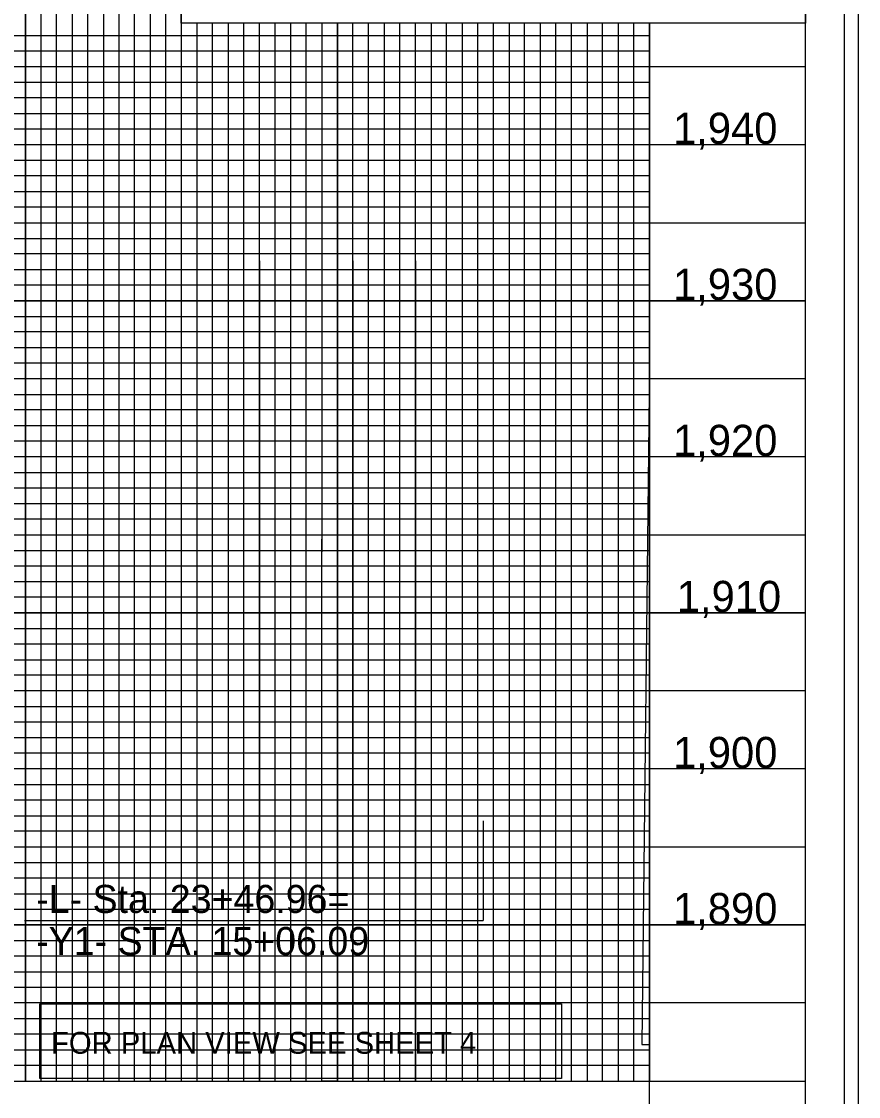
# Model space of a CAD drawing. Extents: x 557032 to 558716, y 513430 to 514605.
# Drawn here: x 558448.2 to 558716.5, y 514000.4 to 514344.9 of the extents above; entities that cross this region are included whole.
import ezdxf

# ---------------------------------------------------------------- set-up
doc = ezdxf.new("R2010")
doc.units = 0
for name, color, linetype in [('Exist Vertical Profile Vertical Axis Label', 7, 'Continuous'), ('Prop VPI Label', 7, 'Continuous'), ('Scratch_Level_5', 7, 'Continuous'), ('Sheet DOT Grid CELL', 7, 'Continuous'), ('Sheet Layout Profile Border Port 1', 7, 'Continuous'), ('Sheet Plot Border Inside CELL', 7, 'Continuous'), ('Sheet Plot Border Outside CELL', 7, 'Continuous'), ('Sheet Profile CELL', 7, 'Continuous'), ('Sheet Profile Grid Major CELL', 7, 'Continuous'), ('Sheet Profile Grid Middle CELL', 7, 'Continuous'), ('Sheet Profile Grid Minor CELL', 7, 'Continuous'), ('Sheet Sticker Exception Certification CELL', 7, 'Continuous')]:
    doc.layers.add(name, color=color, linetype=linetype)

msp = doc.modelspace()

# ---------------------------------------------------------------- linework, layer by layer
at = {"layer": 'Prop VPI Label'}
for p in [(558596.13, 514088.8), (558449.21, 514056.88)]:
    msp.add_line(p, (558596.2, 514056.88), dxfattribs=at)
msp.add_lwpolyline([(558454.04, 514030.1), (558621.32, 514030.1), (558621.32, 514006.16), (558454.04, 514006.16)], close=True, dxfattribs=at)
msp.add_lwpolyline([(558454.04, 514030.1), (558621.32, 514030.1), (558621.32, 514006.16), (558454.04, 514006.16)], close=True, dxfattribs=at)
at = {"layer": 'Scratch_Level_5'}
for p, q in [((558649.45, 514235.4), (558646.99, 514017.12)), ((558649.45, 514017.12), (558649.45, 514235.4)), ((558646.99, 514017.12), (558649.45, 514017.12))]:
    msp.add_line(p, q, dxfattribs=at)
msp.add_lwpolyline([(557207.08, 514505.4), (557207.08, 513980.4), (558649.45, 513980.4), (558649.45, 514344.35), (558499.4, 514344.35), (558499.4, 514505.4)], close=True, dxfattribs=at)
at = {"layer": 'Sheet DOT Grid CELL'}
for p, q in [((558449.45, 514005.4), (558449.45, 514505.4)), ((558449.45, 514036.11), (558449.45, 514488.82)), ((558499.45, 514005.4), (558499.45, 514367.85)), ((558549.45, 514005.4), (558549.45, 514344.35)), ((558599.45, 514005.4), (558599.45, 514344.35)), ((558649.45, 514005.4), (558649.45, 514344.35)), ((558649.45, 514017.12), (558649.45, 514325.22)), ((558599.45, 514039.15), (558599.45, 514322.81)), ((558499.45, 514037.12), (558499.45, 514318.01)), ((558549.45, 514038.14), (558549.45, 514320.41)), ((558699.45, 514305.4), (557199.45, 514305.4)), ((558693.5, 514305.4), (557204.01, 514305.4)), ((558699.45, 514255.4), (557199.45, 514255.4)), ((558693.5, 514255.4), (557204.1, 514255.4)), ((558699.45, 514205.4), (557199.45, 514205.4)), ((558693.5, 514205.4), (557204.18, 514205.4)), ((558699.45, 514155.4), (557199.45, 514155.4)), ((558693.5, 514155.4), (557204.27, 514155.4)), ((558699.45, 514105.4), (557199.45, 514105.4)), ((558693.5, 514105.4), (557204.36, 514105.4)), ((558699.45, 514055.4), (557199.45, 514055.4)), ((558693.5, 514055.4), (557204.45, 514055.4))]:
    msp.add_line(p, q, dxfattribs=at)
at = {"layer": 'Sheet Layout Profile Border Port 1'}
for points in [[(557249.45, 514344.35), (557249.45, 514005.4), (558649.45, 514005.4), (558649.45, 514344.35)], [(558649.45, 514017.12), (558649.45, 514325.22)]]:
    msp.add_lwpolyline(points, dxfattribs=at)
at = {"layer": 'Sheet Plot Border Inside CELL'}
msp.add_lwpolyline([(557045.45, 513452.85), (558711.95, 513452.85), (558711.95, 514507.95), (557045.45, 514507.95)], close=True, dxfattribs=at)
at = {"layer": 'Sheet Plot Border Outside CELL'}
msp.add_lwpolyline([(557032.45, 513430.4), (558716.45, 513430.4), (558716.45, 514530.4), (557032.45, 514530.4)], close=True, dxfattribs=at)
at = {"layer": 'Sheet Profile CELL'}
msp.add_line((557199.45, 514005.4), (558699.45, 514005.4), dxfattribs=at)
msp.add_lwpolyline([(558699.45, 514505.4), (557199.45, 514505.4), (557199.45, 513455.4), (558699.45, 513455.4)], close=True, dxfattribs=at)
at = {"layer": 'Sheet Profile Grid Major CELL'}
for points in [[(557949.45, 514005.4), (557999.45, 514005.4), (557999.45, 514505.4), (558049.45, 514505.4), (558049.45, 514005.4), (558099.45, 514005.4), (558099.45, 514505.4), (558149.45, 514505.4), (558149.45, 514005.4), (558199.45, 514005.4), (558199.45, 514505.4), (558249.45, 514505.4), (558249.45, 514005.4), (558299.45, 514005.4), (558299.45, 514505.4), (558349.45, 514505.4), (558349.45, 514005.4), (558399.45, 514005.4), (558399.45, 514505.4), (558449.45, 514505.4), (558449.45, 514005.4), (558499.45, 514005.4), (558499.45, 514505.4), (558525.75, 514505.4)], [(558449.45, 514488.82), (558449.45, 514036.11)], [(558649.45, 514344.35), (558649.45, 514005.4), (558699.45, 514005.4), (558699.45, 514355.4)], [(558549.45, 514344.35), (558549.45, 514005.4), (558599.45, 514005.4), (558599.45, 514005.4), (558599.45, 514344.35)], [(558649.45, 514325.22), (558649.45, 514017.12)], [(558599.45, 514039.15), (558599.45, 514322.81)], [(558499.45, 514037.12), (558499.45, 514318.01)], [(558549.45, 514320.41), (558549.45, 514038.14)], [(558699.45, 514305.4), (557199.45, 514305.4), (557199.45, 514255.4), (558699.45, 514255.4)], [(558693.5, 514305.4), (557204.01, 514305.4)], [(557204.1, 514255.4), (558693.5, 514255.4)], [(558699.45, 514205.4), (557199.45, 514205.4), (557199.45, 514155.4), (558699.45, 514155.4)], [(558693.5, 514205.4), (557204.18, 514205.4)], [(557204.27, 514155.4), (558693.5, 514155.4)], [(558699.45, 514105.4), (557199.45, 514105.4), (557199.45, 514105.4), (557199.45, 514055.4), (558699.45, 514055.4)], [(558693.5, 514105.4), (557204.36, 514105.4)], [(557204.45, 514055.4), (558693.5, 514055.4)]]:
    msp.add_lwpolyline(points, dxfattribs=at)
at = {"layer": 'Sheet Profile Grid Middle CELL'}
for points in [[(558424.45, 514505.4), (558474.45, 514505.4), (558474.45, 514005.4), (558524.45, 514005.4), (558524.45, 514344.35)], [(558474.45, 514488.82), (558474.45, 514036.62)], [(558524.45, 514268.2), (558524.45, 514005.4), (558574.45, 514005.4), (558574.45, 514344.35)], [(558574.45, 514268.2), (558574.45, 514005.4), (558624.45, 514005.4), (558624.45, 514344.35)], [(558699.45, 514330.4), (557199.45, 514330.4), (557199.45, 514280.4), (558524.45, 514280.4)], [(558484.51, 514330.4), (557203.96, 514330.4)], [(558574.45, 514038.64), (558574.45, 514321.61)], [(558624.45, 514031.91), (558624.45, 514324.01)], [(558524.45, 514037.63), (558524.45, 514319.21)], [(557204.05, 514280.4), (558524.45, 514280.4)], [(558524.45, 514280.4), (558699.45, 514280.4)], [(558524.45, 514280.4), (558693.5, 514280.4)], [(558524.45, 514268.2), (558524.45, 514037.63)], [(558574.45, 514268.2), (558574.45, 514038.64)], [(558699.45, 514230.4), (557199.45, 514230.4), (557199.45, 514180.4), (558699.45, 514180.4)], [(558693.5, 514230.4), (557204.14, 514230.4)], [(557204.23, 514180.4), (558693.5, 514180.4)], [(558699.45, 514130.4), (557199.45, 514130.4), (557199.45, 514080.4), (558699.45, 514080.4)], [(558693.5, 514130.4), (557204.32, 514130.4)], [(557204.4, 514080.4), (558693.5, 514080.4)], [(558699.45, 514030.4), (557199.45, 514030.4)], [(558693.5, 514030.4), (558625.78, 514030.4)]]:
    msp.add_lwpolyline(points, dxfattribs=at)
at = {"layer": 'Sheet Profile Grid Minor CELL'}
for p, q in [((557249.45, 514340.4), (558649.45, 514340.4)), ((557249.45, 514340.4), (558484.51, 514340.4)), ((558649.45, 514320.4), (557249.45, 514320.4)), ((558484.51, 514320.4), (557249.45, 514320.4)), ((558649.45, 514320.4), (558549.26, 514320.4)), ((557249.45, 514315.4), (558649.45, 514315.4)), ((557249.45, 514315.4), (558649.45, 514315.4)), ((558649.45, 514295.4), (557249.45, 514295.4)), ((558649.45, 514295.4), (557249.45, 514295.4)), ((557249.45, 514290.4), (558649.45, 514290.4)), ((557249.45, 514290.4), (558649.45, 514290.4)), ((558649.45, 514270.4), (557249.45, 514270.4)), ((558649.45, 514270.4), (557249.45, 514270.4)), ((557249.45, 514265.4), (558649.45, 514265.4)), ((557249.45, 514265.4), (558649.45, 514265.4)), ((558649.45, 514260.4), (557249.45, 514260.4)), ((558649.45, 514260.4), (557249.45, 514260.4)), ((557249.45, 514250.4), (558649.45, 514250.4)), ((557249.45, 514250.4), (558649.45, 514250.4)), ((558649.45, 514245.4), (557249.45, 514245.4)), ((558649.45, 514245.4), (557249.45, 514245.4)), ((557249.45, 514240.4), (558649.45, 514240.4)), ((557249.45, 514240.4), (558649.45, 514240.4)), ((558649.45, 514235.4), (557249.45, 514235.4)), ((558649.45, 514235.4), (557249.45, 514235.4)), ((557249.45, 514225.4), (558649.45, 514225.4)), ((557249.45, 514225.4), (558649.45, 514225.4)), ((558649.45, 514220.4), (557249.45, 514220.4)), ((558649.45, 514220.4), (557249.45, 514220.4)), ((557249.45, 514215.4), (558649.45, 514215.4)), ((557249.45, 514215.4), (558649.45, 514215.4)), ((558649.45, 514210.4), (557249.45, 514210.4)), ((558649.45, 514210.4), (557249.45, 514210.4)), ((557249.45, 514200.4), (558649.45, 514200.4)), ((557249.45, 514200.4), (558649.45, 514200.4)), ((558649.45, 514195.4), (557249.45, 514195.4)), ((558649.45, 514195.4), (557249.45, 514195.4)), ((557249.45, 514190.4), (558649.45, 514190.4)), ((557249.45, 514190.4), (558649.45, 514190.4)), ((558649.45, 514185.4), (557249.45, 514185.4)), ((558649.45, 514185.4), (557249.45, 514185.4)), ((557249.45, 514175.4), (558649.45, 514175.4)), ((557249.45, 514175.4), (558649.45, 514175.4)), ((558649.45, 514170.4), (557249.45, 514170.4)), ((558649.45, 514170.4), (557249.45, 514170.4)), ((557249.45, 514165.4), (558649.45, 514165.4)), ((557249.45, 514165.4), (558649.45, 514165.4)), ((558649.45, 514160.4), (557249.45, 514160.4)), ((558649.45, 514160.4), (557249.45, 514160.4)), ((557249.45, 514150.4), (558649.45, 514150.4)), ((557249.45, 514150.4), (558649.45, 514150.4)), ((558649.45, 514145.4), (557249.45, 514145.4)), ((558649.45, 514145.4), (557249.45, 514145.4)), ((557249.45, 514140.4), (558649.45, 514140.4)), ((557249.45, 514140.4), (558649.45, 514140.4)), ((558649.45, 514135.4), (557249.45, 514135.4)), ((558649.45, 514135.4), (557249.45, 514135.4)), ((557249.45, 514125.4), (558649.45, 514125.4)), ((557249.45, 514125.4), (558649.45, 514125.4)), ((558649.45, 514120.4), (557249.45, 514120.4)), ((558649.45, 514120.4), (557249.45, 514120.4)), ((558649.45, 514115.4), (557249.45, 514115.4)), ((558649.45, 514115.4), (557249.45, 514115.4)), ((558649.45, 514110.4), (557249.45, 514110.4)), ((558649.45, 514110.4), (557249.45, 514110.4)), ((557249.45, 514100.4), (558649.45, 514100.4)), ((557249.45, 514100.4), (558649.45, 514100.4)), ((558649.45, 514095.4), (557249.45, 514095.4)), ((558649.45, 514095.4), (557249.45, 514095.4)), ((557249.45, 514090.4), (558649.45, 514090.4)), ((557249.45, 514090.4), (558649.45, 514090.4)), ((558649.45, 514085.4), (557249.45, 514085.4)), ((558649.45, 514085.4), (557249.45, 514085.4)), ((557249.45, 514075.4), (558649.45, 514075.4)), ((557249.45, 514075.4), (558649.45, 514075.4)), ((558649.45, 514070.4), (557249.45, 514070.4)), ((558649.45, 514070.4), (557249.45, 514070.4)), ((557249.45, 514065.4), (558649.45, 514065.4)), ((557249.45, 514065.4), (558649.45, 514065.4)), ((558649.45, 514060.4), (557249.45, 514060.4)), ((558649.45, 514060.4), (557249.45, 514060.4)), ((557249.45, 514050.4), (558649.45, 514050.4)), ((557249.45, 514050.4), (558649.45, 514050.4)), ((558649.45, 514045.4), (557249.45, 514045.4)), ((558649.45, 514045.4), (557249.45, 514045.4)), ((557249.45, 514040.4), (558649.45, 514040.4)), ((557249.45, 514040.4), (558649.45, 514040.4)), ((558649.45, 514035.4), (557249.45, 514035.4)), ((558649.45, 514035.4), (558621.36, 514035.4)), ((557249.45, 514025.4), (558649.45, 514025.4)), ((558630.2, 514025.4), (558649.45, 514025.4)), ((558649.45, 514020.4), (557249.45, 514020.4)), ((558649.45, 514020.4), (558634.63, 514020.4)), ((557249.45, 514015.4), (558649.45, 514015.4))]:
    msp.add_line(p, q, dxfattribs=at)
for points in [[(558444.45, 514505.4), (558454.45, 514505.4), (558454.45, 514005.4), (558459.45, 514005.4), (558459.45, 514505.4), (558464.45, 514505.4), (558464.45, 514005.4), (558469.45, 514005.4), (558469.45, 514505.4), (558479.45, 514505.4), (558479.45, 514005.4), (558484.45, 514005.4), (558484.45, 514505.4), (558489.45, 514505.4), (558489.45, 514005.4), (558494.45, 514005.4), (558494.45, 514505.4), (558504.45, 514505.4)], [(558454.45, 514488.82), (558454.45, 514036.21)], [(558459.45, 514036.31), (558459.45, 514488.82)], [(558464.45, 514488.82), (558464.45, 514036.42)], [(558469.45, 514036.52), (558469.45, 514488.82)], [(558479.45, 514488.82), (558479.45, 514036.72)], [(558484.45, 514036.82), (558484.45, 514488.82)], [(558504.45, 514344.35), (558504.45, 514005.4), (558509.45, 514005.4), (558509.45, 514344.35)], [(558514.45, 514344.35), (558514.45, 514005.4), (558519.45, 514005.4), (558519.45, 514344.35)], [(558529.45, 514344.35), (558529.45, 514005.4), (558529.45, 514005.4), (558534.45, 514005.4), (558539.45, 514005.4), (558539.45, 514344.35)], [(558534.45, 514344.35), (558534.45, 514005.4)], [(558544.45, 514344.35), (558544.35, 514005.45), (558549.35, 514005.45), (558554.45, 514005.4), (558554.45, 514344.35)], [(558554.45, 514268.2), (558554.45, 514005.4), (558559.45, 514005.4), (558559.45, 514344.35)], [(558564.45, 514344.35), (558564.45, 514005.4), (558569.45, 514005.4), (558569.45, 514344.35)], [(558579.45, 514344.35), (558579.45, 514005.4), (558584.45, 514005.4), (558584.45, 514344.35)], [(558589.45, 514344.35), (558589.45, 514005.4), (558594.45, 514005.4), (558594.45, 514344.35)], [(558604.45, 514344.35), (558604.45, 514005.4), (558609.45, 514005.4), (558609.45, 514344.35)], [(558614.45, 514344.35), (558614.45, 514005.4), (558619.45, 514005.4), (558619.45, 514344.35)], [(558629.45, 514344.35), (558629.45, 514005.4), (558634.45, 514005.4), (558634.45, 514344.35)], [(558639.45, 514344.35), (558639.45, 514005.4), (558644.45, 514005.4), (558644.45, 514344.35)], [(558649.45, 514335.4), (557249.45, 514335.4), (557249.45, 514325.4), (558649.45, 514325.4)], [(558484.51, 514335.4), (557249.45, 514335.4), (557249.45, 514325.4), (558484.51, 514325.4)], [(558629.45, 514324.25), (558629.45, 514026.25)], [(558634.45, 514020.59), (558634.45, 514324.49)], [(558639.45, 514324.74), (558639.45, 514017.12)], [(558644.45, 514017.12), (558644.45, 514324.98)], [(558559.45, 514038.34), (558559.45, 514320.89)], [(558564.45, 514321.13), (558564.45, 514038.44)], [(558569.45, 514038.54), (558569.45, 514321.37)], [(558579.45, 514321.85), (558579.45, 514038.75)], [(558584.45, 514038.85), (558584.45, 514322.09)], [(558589.45, 514322.33), (558589.45, 514038.95)], [(558594.45, 514039.05), (558594.45, 514322.57)], [(558604.45, 514323.05), (558604.45, 514039.25)], [(558609.45, 514039.35), (558609.45, 514323.29)], [(558614.45, 514323.53), (558614.45, 514039.46)], [(558619.45, 514037.56), (558619.45, 514323.77)], [(558489.45, 514317.53), (558489.45, 514036.92)], [(558494.45, 514037.02), (558494.45, 514317.77)], [(558504.45, 514318.25), (558504.45, 514037.23)], [(558509.45, 514037.33), (558509.45, 514318.49)], [(558514.45, 514318.73), (558514.45, 514037.43)], [(558519.45, 514037.53), (558519.45, 514318.97)], [(558529.45, 514319.45), (558529.45, 514037.73)], [(558534.45, 514319.69), (558534.45, 514037.83)], [(558539.45, 514037.94), (558539.45, 514319.93)], [(558544.44, 514320.17), (558544.36, 514038.04)], [(558554.45, 514038.24), (558554.45, 514320.65)], [(558649.45, 514310.4), (557249.45, 514310.4), (557249.45, 514300.4), (558649.45, 514300.4)], [(558649.45, 514310.4), (557249.45, 514310.4), (557249.45, 514300.4), (558649.45, 514300.4)], [(558649.45, 514285.4), (557249.45, 514285.4), (557249.45, 514275.4), (558649.45, 514275.4)], [(558649.45, 514285.4), (557249.45, 514285.4), (557249.45, 514275.4), (558649.45, 514275.4)], [(558554.45, 514268.2), (558554.45, 514038.24)], [(558649.45, 514010.4), (557249.45, 514010.4)]]:
    msp.add_lwpolyline(points, dxfattribs=at)
at = {"layer": 'Sheet Sticker Exception Certification CELL'}
for p, q in [((558499.4, 514344.35), (558499.4, 514367.85)), ((558499.4, 514344.35), (558499.4, 514367.85)), ((558699.44, 514367.84), (558699.44, 514344.34)), ((558699.44, 514367.84), (558699.44, 514344.34)), ((558699.44, 514344.35), (558499.4, 514344.35)), ((558699.44, 514344.35), (558499.4, 514344.35))]:
    msp.add_line(p, q, dxfattribs=at)

# ---------------------------------------------------------------- texts
at = {"layer": 'Exist Vertical Profile Vertical Axis Label'}
for s, p in [('1,940', (558657.01, 514305.65)), ('1,940', (558657.01, 514305.65)), ('1,940', (558657.01, 514305.65)), ('1,940', (558657.01, 514305.65)), ('1,930', (558657.01, 514255.65)), ('1,930', (558657.01, 514255.65)), ('1,930', (558657.01, 514255.65)), ('1,930', (558657.01, 514255.65)), ('1,920', (558657.01, 514205.65)), ('1,920', (558657.01, 514205.65)), ('1,920', (558657.01, 514205.65)), ('1,920', (558657.01, 514205.65)), ('1,910', (558658.21, 514155.65)), ('1,910', (558658.21, 514155.65)), ('1,910', (558658.21, 514155.65)), ('1,910', (558658.21, 514155.65)), ('1,900', (558657.01, 514105.65)), ('1,900', (558657.01, 514105.65)), ('1,900', (558657.01, 514105.65)), ('1,900', (558657.01, 514105.65)), ('1,890', (558657.01, 514055.65)), ('1,890', (558657.01, 514055.65)), ('1,890', (558657.01, 514055.65)), ('1,890', (558657.01, 514055.65))]:
    msp.add_text(s, height=10, dxfattribs=at).set_placement(p)
at = {"layer": 'Prop VPI Label'}
for s, height, p in [('-L- Sta. 23+46.96=', 9, (558452.93, 514059.24)), ('-Y1- STA. 15+06.09', 9, (558452.93, 514045.74)), ('FOR PLAN VIEW SEE SHEET 4', 7, (558457.69, 514014.14))]:
    msp.add_text(s, height=height, dxfattribs=at).set_placement(p)

doc.saveas('drawing.dxf')
